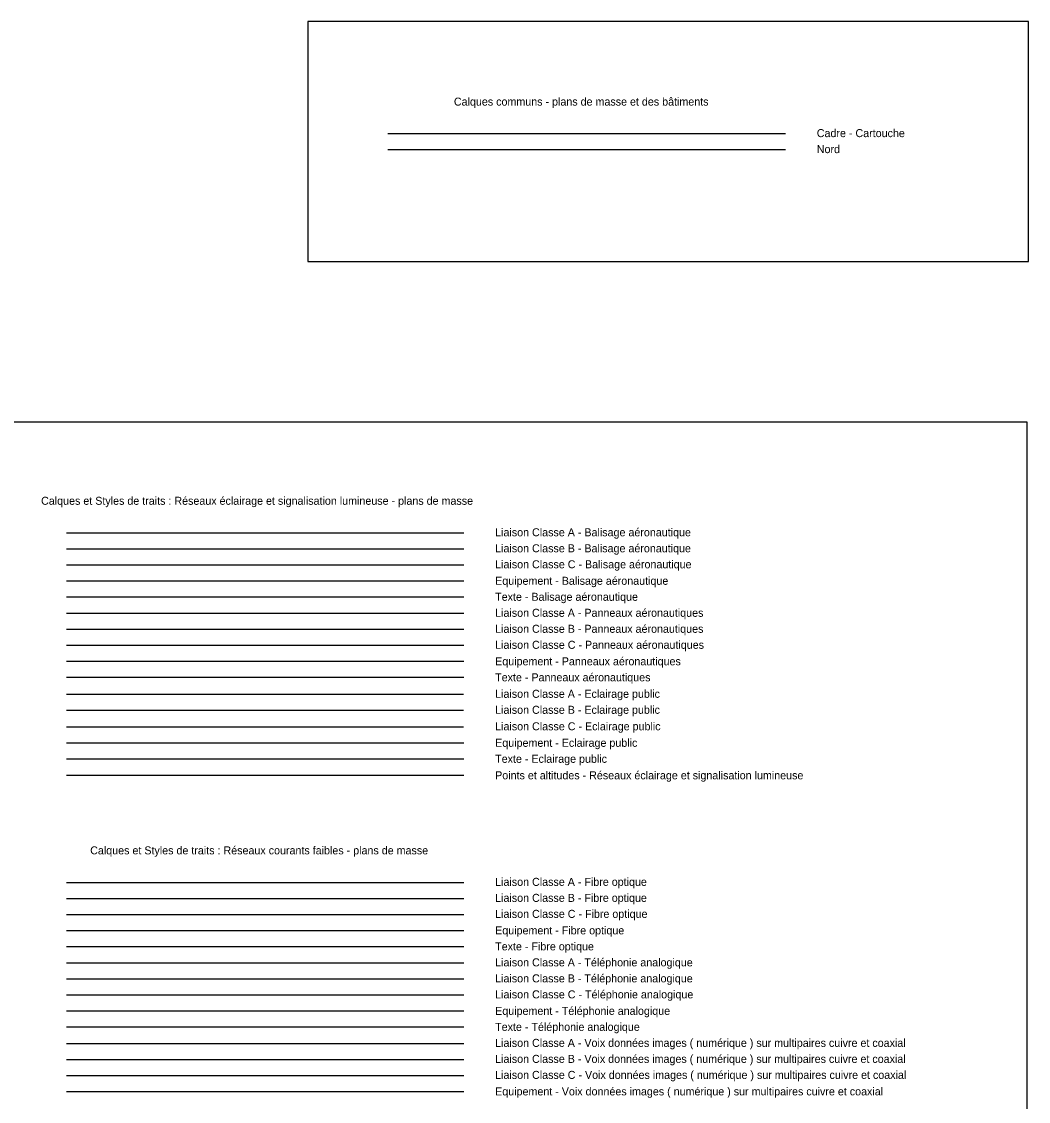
# Model space of a CAD drawing. Extents: x 703432 to 707394, y 7057985 to 7059523.
# Drawn here: x 707261.7 to 707324.6, y 7058602.1 to 7058669.6 of the extents above; entities that cross this region are included whole.
import ezdxf

# ---------------------------------------------------------------- set-up
doc = ezdxf.new("R2010")
doc.units = 0
for name, color, linetype in [('DH_CADRE -CARTOUCHE', 7, 'Continuous'), ('DH_NORD', 7, 'Continuous'), ('R_CF_FO_CANALISATION_CL_A', 7, 'Continuous'), ('R_CF_FO_CANALISATION_CL_B', 7, 'Continuous'), ('R_CF_FO_CANALISATION_CL_C', 7, 'Continuous'), ('R_CF_FO_EQUIP', 7, 'Continuous'), ('R_CF_FO_TEXTE', 7, 'Continuous'), ('R_CF_TEL_EQUIP', 7, 'Continuous'), ('R_CF_TEL_LIAISON_CL_A', 7, 'Continuous'), ('R_CF_TEL_LIAISON_CL_B', 7, 'Continuous'), ('R_CF_TEL_LIAISON_CL_C', 7, 'Continuous'), ('R_CF_TEL_TEXTE', 7, 'Continuous'), ('R_CF_VDI_EQUIP', 7, 'Continuous'), ('R_CF_VDI_LIAISON_CL_A', 7, 'Continuous'), ('R_CF_VDI_LIAISON_CL_B', 7, 'Continuous'), ('R_CF_VDI_LIAISON_CL_C', 7, 'Continuous'), ('R_ECLAIR_AERO_EQUIP', 7, 'Continuous'), ('R_ECLAIR_AERO_LIAISON_CL_A', 7, 'Continuous'), ('R_ECLAIR_AERO_LIAISON_CL_B', 7, 'Continuous'), ('R_ECLAIR_AERO_LIAISON_CL_C', 7, 'Continuous'), ('R_ECLAIR_AERO_TEXTE', 7, 'Continuous'), ('R_ECLAIR_ALT_POINT', 7, 'Continuous'), ('R_ECLAIR_PANNEAU_AERO_EQUIP', 7, 'Continuous'), ('R_ECLAIR_PANNEAU_AERO_LIAISON_CL_A', 7, 'Continuous'), ('R_ECLAIR_PANNEAU_AERO_LIAISON_CL_B', 7, 'Continuous'), ('R_ECLAIR_PANNEAU_AERO_LIAISON_CL_C', 7, 'Continuous'), ('R_ECLAIR_PANNEAU_AERO_TEXTE', 7, 'Continuous'), ('R_ECLAIR_PUB_EQUIP', 7, 'Continuous'), ('R_ECLAIR_PUB_LIAISON_CL_A', 7, 'Continuous'), ('R_ECLAIR_PUB_LIAISON_CL_B', 7, 'Continuous'), ('R_ECLAIR_PUB_LIAISON_CL_C', 7, 'Continuous'), ('R_ECLAIR_PUB_TEXTE', 7, 'Continuous')]:
    doc.layers.add(name, color=color, linetype=linetype)

msp = doc.modelspace()

# ---------------------------------------------------------------- linework, layer by layer
at = {"layer": 'DH_CADRE -CARTOUCHE'}
msp.add_line((707284.559, 7058662.551), (707309.379, 7058662.551), dxfattribs=at)
for points in [[(707279.559, 7058654.551), (707324.559, 7058654.551), (707324.559, 7058669.551), (707279.559, 7058669.551)], [(707199.469, 7058644.551), (707324.469, 7058644.551), (707324.469, 7058419.551), (707199.469, 7058419.551)]]:
    msp.add_lwpolyline(points, close=True, dxfattribs=at)
at = {"layer": 'DH_NORD'}
msp.add_line((707284.559, 7058661.551), (707309.379, 7058661.551), dxfattribs=at)
at = {"layer": 'R_CF_FO_CANALISATION_CL_A'}
msp.add_line((707264.469, 7058615.763), (707289.289, 7058615.763), dxfattribs=at)
at = {"layer": 'R_CF_FO_CANALISATION_CL_B'}
msp.add_line((707264.469, 7058614.763), (707289.289, 7058614.763), dxfattribs=at)
at = {"layer": 'R_CF_FO_CANALISATION_CL_C'}
msp.add_line((707264.469, 7058613.763), (707289.289, 7058613.763), dxfattribs=at)
at = {"layer": 'R_CF_FO_EQUIP'}
msp.add_line((707264.469, 7058612.763), (707289.298, 7058612.763), dxfattribs=at)
at = {"layer": 'R_CF_FO_TEXTE'}
msp.add_line((707264.469, 7058611.763), (707289.298, 7058611.763), dxfattribs=at)
at = {"layer": 'R_CF_TEL_EQUIP'}
msp.add_line((707264.469, 7058607.732), (707289.298, 7058607.732), dxfattribs=at)
at = {"layer": 'R_CF_TEL_LIAISON_CL_A'}
msp.add_line((707264.469, 7058610.732), (707289.289, 7058610.732), dxfattribs=at)
at = {"layer": 'R_CF_TEL_LIAISON_CL_B'}
msp.add_line((707264.469, 7058609.732), (707289.289, 7058609.732), dxfattribs=at)
at = {"layer": 'R_CF_TEL_LIAISON_CL_C'}
msp.add_line((707264.469, 7058608.732), (707289.289, 7058608.732), dxfattribs=at)
at = {"layer": 'R_CF_TEL_TEXTE'}
msp.add_line((707264.469, 7058606.732), (707289.298, 7058606.732), dxfattribs=at)
at = {"layer": 'R_CF_VDI_EQUIP'}
msp.add_line((707264.469, 7058602.701), (707289.298, 7058602.701), dxfattribs=at)
at = {"layer": 'R_CF_VDI_LIAISON_CL_A'}
msp.add_line((707264.469, 7058605.701), (707289.289, 7058605.701), dxfattribs=at)
at = {"layer": 'R_CF_VDI_LIAISON_CL_B'}
msp.add_line((707264.469, 7058604.701), (707289.289, 7058604.701), dxfattribs=at)
at = {"layer": 'R_CF_VDI_LIAISON_CL_C'}
msp.add_line((707264.469, 7058603.701), (707289.289, 7058603.701), dxfattribs=at)
at = {"layer": 'R_ECLAIR_AERO_EQUIP'}
msp.add_line((707264.469, 7058634.608), (707289.298, 7058634.608), dxfattribs=at)
at = {"layer": 'R_ECLAIR_AERO_LIAISON_CL_A'}
msp.add_line((707264.469, 7058637.608), (707289.289, 7058637.608), dxfattribs=at)
at = {"layer": 'R_ECLAIR_AERO_LIAISON_CL_B'}
msp.add_line((707264.469, 7058636.608), (707289.289, 7058636.608), dxfattribs=at)
at = {"layer": 'R_ECLAIR_AERO_LIAISON_CL_C'}
msp.add_line((707264.469, 7058635.608), (707289.289, 7058635.608), dxfattribs=at)
at = {"layer": 'R_ECLAIR_AERO_TEXTE'}
msp.add_line((707264.469, 7058633.608), (707289.298, 7058633.608), dxfattribs=at)
at = {"layer": 'R_ECLAIR_ALT_POINT'}
msp.add_line((707264.469, 7058622.453), (707289.298, 7058622.453), dxfattribs=at)
at = {"layer": 'R_ECLAIR_PANNEAU_AERO_EQUIP'}
msp.add_line((707264.469, 7058629.577), (707289.298, 7058629.577), dxfattribs=at)
at = {"layer": 'R_ECLAIR_PANNEAU_AERO_LIAISON_CL_A'}
msp.add_line((707264.469, 7058632.577), (707289.289, 7058632.577), dxfattribs=at)
at = {"layer": 'R_ECLAIR_PANNEAU_AERO_LIAISON_CL_B'}
msp.add_line((707264.469, 7058631.577), (707289.289, 7058631.577), dxfattribs=at)
at = {"layer": 'R_ECLAIR_PANNEAU_AERO_LIAISON_CL_C'}
msp.add_line((707264.469, 7058630.577), (707289.289, 7058630.577), dxfattribs=at)
at = {"layer": 'R_ECLAIR_PANNEAU_AERO_TEXTE'}
msp.add_line((707264.469, 7058628.577), (707289.298, 7058628.577), dxfattribs=at)
at = {"layer": 'R_ECLAIR_PUB_EQUIP'}
msp.add_line((707264.469, 7058624.484), (707289.298, 7058624.484), dxfattribs=at)
at = {"layer": 'R_ECLAIR_PUB_LIAISON_CL_A'}
msp.add_line((707264.469, 7058627.515), (707289.269, 7058627.515), dxfattribs=at)
at = {"layer": 'R_ECLAIR_PUB_LIAISON_CL_B'}
msp.add_line((707264.469, 7058626.515), (707289.269, 7058626.515), dxfattribs=at)
at = {"layer": 'R_ECLAIR_PUB_LIAISON_CL_C'}
msp.add_line((707264.469, 7058625.484), (707289.269, 7058625.484), dxfattribs=at)
at = {"layer": 'R_ECLAIR_PUB_TEXTE'}
msp.add_line((707264.469, 7058623.484), (707289.298, 7058623.484), dxfattribs=at)

# ---------------------------------------------------------------- texts
at = {"layer": 'DH_CADRE -CARTOUCHE'}
for s, p in [('Calques communs - plans de masse et des bâtiments', (707288.675, 7058664.301)), ('Cadre - Cartouche', (707311.342, 7058662.332)), (' Calques et Styles de traits : Réseaux éclairage et signalisation lumineuse - plans de masse', (707262.705, 7058639.358)), (' Calques et Styles de traits : Réseaux courants faibles - plans de masse', (707265.772, 7058617.513))]:
    msp.add_text(s, height=0.5, dxfattribs=at).set_placement(p)
at = {"layer": 'DH_NORD'}
msp.add_text('Nord', height=0.5, dxfattribs=at).set_placement((707311.342, 7058661.332))
at = {"layer": 'R_CF_FO_CANALISATION_CL_A'}
msp.add_text('Liaison Classe A - Fibre optique', height=0.5, dxfattribs=at).set_placement((707291.252, 7058615.544))
at = {"layer": 'R_CF_FO_CANALISATION_CL_B'}
msp.add_text('Liaison Classe B - Fibre optique', height=0.5, dxfattribs=at).set_placement((707291.252, 7058614.544))
at = {"layer": 'R_CF_FO_CANALISATION_CL_C'}
msp.add_text('Liaison Classe C - Fibre optique', height=0.5, dxfattribs=at).set_placement((707291.252, 7058613.544))
at = {"layer": 'R_CF_FO_EQUIP'}
msp.add_text('Equipement - Fibre optique', height=0.5, dxfattribs=at).set_placement((707291.252, 7058612.513))
at = {"layer": 'R_CF_FO_TEXTE'}
msp.add_text('Texte - Fibre optique', height=0.5, dxfattribs=at).set_placement((707291.252, 7058611.513))
at = {"layer": 'R_CF_TEL_EQUIP'}
msp.add_text('Equipement - Téléphonie analogique', height=0.5, dxfattribs=at).set_placement((707291.252, 7058607.482))
at = {"layer": 'R_CF_TEL_LIAISON_CL_A'}
msp.add_text('Liaison Classe A - Téléphonie analogique', height=0.5, dxfattribs=at).set_placement((707291.252, 7058610.513))
at = {"layer": 'R_CF_TEL_LIAISON_CL_B'}
msp.add_text('Liaison Classe B - Téléphonie analogique', height=0.5, dxfattribs=at).set_placement((707291.252, 7058609.513))
at = {"layer": 'R_CF_TEL_LIAISON_CL_C'}
msp.add_text('Liaison Classe C - Téléphonie analogique', height=0.5, dxfattribs=at).set_placement((707291.252, 7058608.513))
at = {"layer": 'R_CF_TEL_TEXTE'}
msp.add_text('Texte - Téléphonie analogique', height=0.5, dxfattribs=at).set_placement((707291.252, 7058606.482))
at = {"layer": 'R_CF_VDI_EQUIP'}
msp.add_text('Equipement - Voix données images ( numérique ) sur multipaires cuivre et coaxial', height=0.5, dxfattribs=at).set_placement((707291.252, 7058602.451))
at = {"layer": 'R_CF_VDI_LIAISON_CL_A'}
msp.add_text('Liaison Classe A - Voix données images ( numérique ) sur multipaires cuivre et coaxial', height=0.5, dxfattribs=at).set_placement((707291.252, 7058605.482))
at = {"layer": 'R_CF_VDI_LIAISON_CL_B'}
msp.add_text('Liaison Classe B - Voix données images ( numérique ) sur multipaires cuivre et coaxial', height=0.5, dxfattribs=at).set_placement((707291.252, 7058604.482))
at = {"layer": 'R_CF_VDI_LIAISON_CL_C'}
msp.add_text('Liaison Classe C - Voix données images ( numérique ) sur multipaires cuivre et coaxial', height=0.5, dxfattribs=at).set_placement((707291.252, 7058603.482))
at = {"layer": 'R_ECLAIR_AERO_EQUIP'}
msp.add_text('Equipement - Balisage aéronautique', height=0.5, dxfattribs=at).set_placement((707291.252, 7058634.358))
at = {"layer": 'R_ECLAIR_AERO_LIAISON_CL_A'}
msp.add_text('Liaison Classe A - Balisage aéronautique', height=0.5, dxfattribs=at).set_placement((707291.252, 7058637.389))
at = {"layer": 'R_ECLAIR_AERO_LIAISON_CL_B'}
msp.add_text('Liaison Classe B - Balisage aéronautique', height=0.5, dxfattribs=at).set_placement((707291.252, 7058636.389))
at = {"layer": 'R_ECLAIR_AERO_LIAISON_CL_C'}
msp.add_text('Liaison Classe C - Balisage aéronautique', height=0.5, dxfattribs=at).set_placement((707291.252, 7058635.389))
at = {"layer": 'R_ECLAIR_AERO_TEXTE'}
msp.add_text('Texte - Balisage aéronautique', height=0.5, dxfattribs=at).set_placement((707291.252, 7058633.358))
at = {"layer": 'R_ECLAIR_ALT_POINT'}
msp.add_text('Points et altitudes - Réseaux éclairage et signalisation lumineuse', height=0.5, dxfattribs=at).set_placement((707291.252, 7058622.203))
at = {"layer": 'R_ECLAIR_PANNEAU_AERO_EQUIP'}
msp.add_text('Equipement - Panneaux aéronautiques', height=0.5, dxfattribs=at).set_placement((707291.252, 7058629.327))
at = {"layer": 'R_ECLAIR_PANNEAU_AERO_LIAISON_CL_A'}
msp.add_text('Liaison Classe A - Panneaux aéronautiques', height=0.5, dxfattribs=at).set_placement((707291.252, 7058632.358))
at = {"layer": 'R_ECLAIR_PANNEAU_AERO_LIAISON_CL_B'}
msp.add_text('Liaison Classe B - Panneaux aéronautiques', height=0.5, dxfattribs=at).set_placement((707291.252, 7058631.358))
at = {"layer": 'R_ECLAIR_PANNEAU_AERO_LIAISON_CL_C'}
msp.add_text('Liaison Classe C - Panneaux aéronautiques', height=0.5, dxfattribs=at).set_placement((707291.252, 7058630.358))
at = {"layer": 'R_ECLAIR_PANNEAU_AERO_TEXTE'}
msp.add_text('Texte - Panneaux aéronautiques', height=0.5, dxfattribs=at).set_placement((707291.252, 7058628.327))
at = {"layer": 'R_ECLAIR_PUB_EQUIP'}
msp.add_text('Equipement - Eclairage public', height=0.5, dxfattribs=at).set_placement((707291.252, 7058624.234))
at = {"layer": 'R_ECLAIR_PUB_LIAISON_CL_A'}
msp.add_text('Liaison Classe A - Eclairage public', height=0.5, dxfattribs=at).set_placement((707291.252, 7058627.296))
at = {"layer": 'R_ECLAIR_PUB_LIAISON_CL_B'}
msp.add_text('Liaison Classe B - Eclairage public', height=0.5, dxfattribs=at).set_placement((707291.252, 7058626.296))
at = {"layer": 'R_ECLAIR_PUB_LIAISON_CL_C'}
msp.add_text('Liaison Classe C - Eclairage public', height=0.5, dxfattribs=at).set_placement((707291.252, 7058625.265))
at = {"layer": 'R_ECLAIR_PUB_TEXTE'}
msp.add_text('Texte - Eclairage public', height=0.5, dxfattribs=at).set_placement((707291.252, 7058623.234))

doc.saveas('drawing.dxf')
